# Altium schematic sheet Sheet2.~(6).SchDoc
size A; SheetNumber: 1; SheetTotal: 1
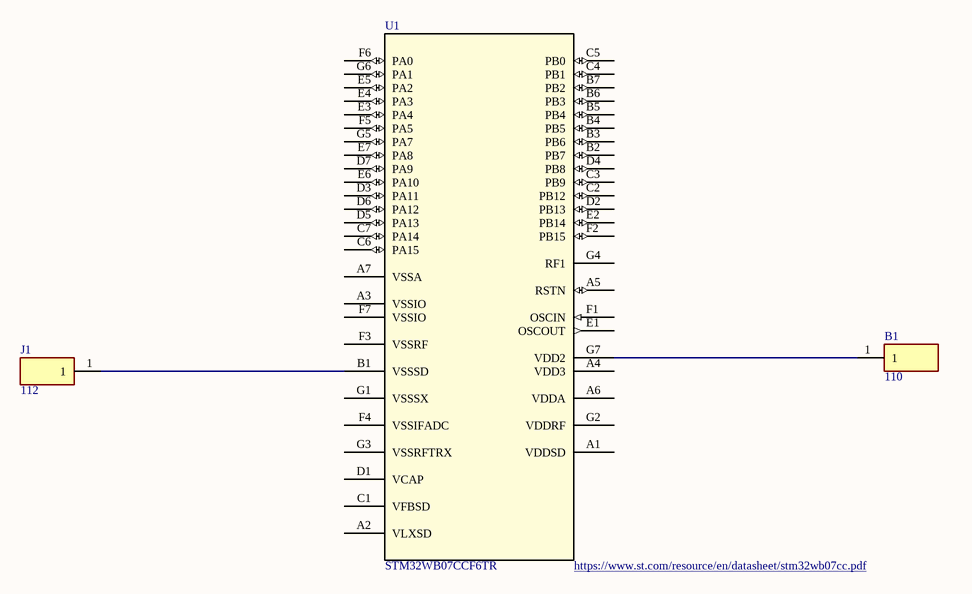
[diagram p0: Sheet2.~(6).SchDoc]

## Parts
B1  110  [110]
J1  112  [112]
U1  STM32WB07CCF6TR  [WLCSP49_7P140X3P140_STM]

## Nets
NetB1_1: B1.1 U1.G7(VDD2)
NetJ1_1: J1.1 U1.B1(VSSSD)

Not connected (* = marked no-connect by the designer): U1 A1(VDDSD) A2(VLXSD) A3(VSSIO) A4(VDD3) A5(RSTN) A6(VDDA) A7(VSSA) B2(PB7) B3(PB6) B4(PB5) B5(PB4) B6(PB3) B7(PB2) C1(VFBSD) C2(PB12) C3(PB9) C4(PB1) C5(PB0) C6(PA15) C7(PA14) D1(VCAP) D2(PB13) D3(PA11) D4(PB8) D5(PA13) D6(PA12) D7(PA9) E1(OSCOUT) E2(PB14) E3(PA4) E4(PA3) E5(PA2) E6(PA10) E7(PA8) F1(OSCIN) F2(PB15) F3(VSSRF) F4(VSSIFADC) F5(PA5) F6(PA0) F7(VSSIO) G1(VSSSX) G2(VDDRF) G3(VSSRFTRX) G4(RF1) G5(PA7) G6(PA1)

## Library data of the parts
B1 = 110: Battery Contacts S/M COIN CELL CNCT POSITIVE 16mm UP; Manufacturer_Name: Keystone Electronics; Geometry.Height: 3.3mm
J1 = 112: Battery Contacts S/M COIN CELL CNCT NEGATIVE 16mm UP; Manufacturer_Name: Keystone Electronics; Geometry.Height: 3mm
U1 = STM32WB07CCF6TR: Ultra-low-power, Arm Cortex-M0+ MCU 64 MHz with 256 Kbytes of Flash memory, 64 Kbytes of RAM,  Bluetooth LE 5.4; Manufacturer_Name: STMicroelectronics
